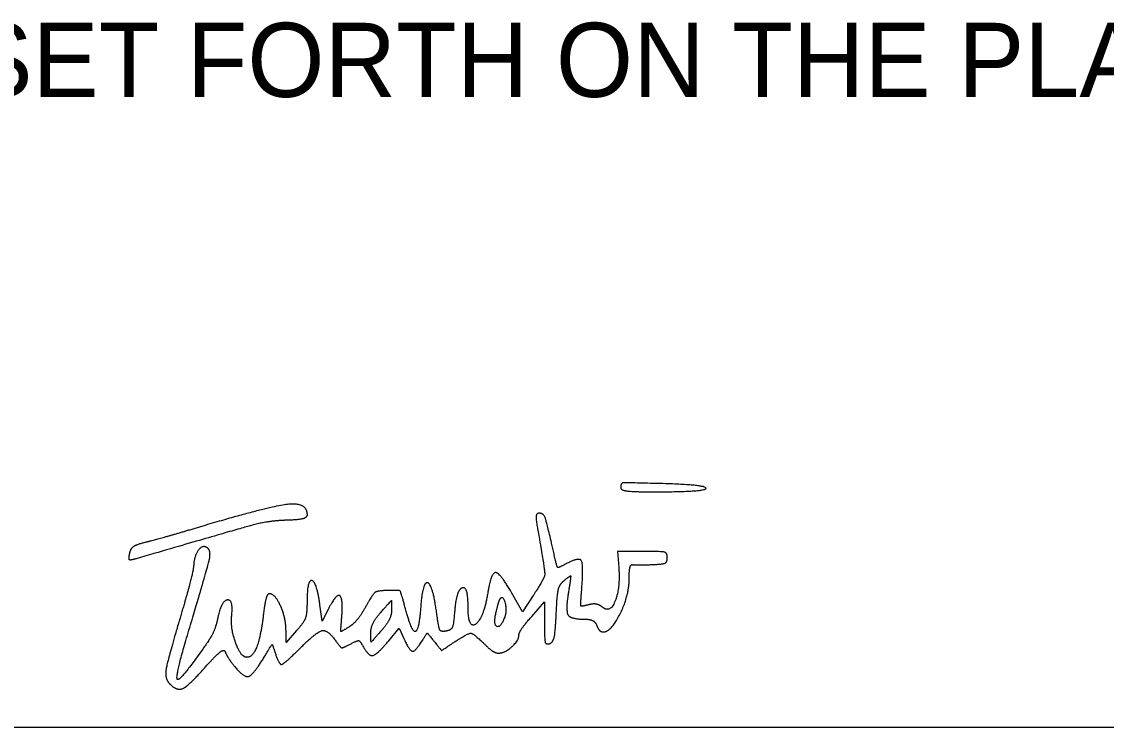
# Model space of a CAD drawing. Extents: x 0 to 34, y 0 to 22.
# Drawn here: x 25.697 to 27.744, y 8.816 to 10.148 of the extents above; entities that cross this region are included whole.
import ezdxf

# ---------------------------------------------------------------- set-up
doc = ezdxf.new("R2010")
doc.units = 0
doc.layers.add('SH_Data', color=7, linetype='Continuous')
doc.layers.add('SH_Text', color=7, linetype='Continuous')

msp = doc.modelspace()

# ---------------------------------------------------------------- linework, layer by layer
at = {"layer": 'SH_Data'}
msp.add_line((24.5, 8.816), (28, 8.816), dxfattribs=at)
at = {"layer": 'SH_Text'}
msp.add_line((25.9008, 9.1444), (25.9008, 9.1444), dxfattribs=at)
for points in [[(26.8687, 9.1481), (26.8218, 9.1481), (26.824, 9.118)], [(26.6626, 9.0651), (26.642, 9.0339), (26.6246, 9.0649)], [(26.6596, 9.0253), (26.6836, 9.0526), (26.6836, 9.0117)], [(26.2754, 9.0383), (26.2644, 9.0161), (26.26, 9.0474)], [(26.2159, 8.9985), (26.1961, 8.9761), (26.1959, 8.9985)], [(26.3899, 8.9795), (26.4096, 9.0029), (26.4184, 8.9835)]]:
    msp.add_lwpolyline(points, dxfattribs=at)
for points in [[(26.9025, 9.2761), (26.8357, 9.2779), (26.8276, 9.277), (26.8276, 9.2681)], [(26.9056, 9.2606), (26.99, 9.2611), (26.9875, 9.2738), (26.9025, 9.2761)], [(26.8276, 9.2681), (26.8276, 9.2633), (26.8586, 9.2603), (26.9056, 9.2606)], [(26.0398, 9.1966), (26.1652, 9.2339), (26.2356, 9.2413), (26.2356, 9.2171)], [(26.2356, 9.2171), (26.2356, 9.2118), (26.2198, 9.2076), (26.1974, 9.2069)], [(26.6743, 9.2201), (26.6684, 9.2201), (26.6675, 9.209), (26.6716, 9.1861)], [(26.703, 9.1379), (26.6886, 9.2017), (26.6822, 9.2201), (26.6743, 9.2201)], [(26.1974, 9.2069), (26.1654, 9.206), (26.1126, 9.1925), (25.9128, 9.1341)], [(25.9316, 9.1659), (25.947, 9.1696), (25.9957, 9.1834), (26.0398, 9.1966)], [(26.6716, 9.1861), (26.6849, 9.1112), (26.6839, 9.0973), (26.6626, 9.0651)], [(25.9008, 9.1444), (25.9026, 9.1535), (25.9143, 9.1617), (25.9316, 9.1659)], [(26.0111, 8.9943), (26.0457, 9.1098), (26.0549, 9.1475), (26.0494, 9.1529)], [(26.0494, 9.1529), (26.0407, 9.1617), (26.0233, 9.1427), (26.0216, 9.1224)], [(25.9128, 9.1341), (25.9017, 9.1309), (25.8987, 9.1334), (25.9008, 9.1444)], [(26.7247, 9.1246), (26.7099, 9.1168), (26.7074, 9.1183), (26.703, 9.1379)], [(26.7544, 9.0804), (26.7578, 9.124), (26.7488, 9.1375), (26.7247, 9.1246)], [(26.9156, 9.1361), (26.9156, 9.1454), (26.9051, 9.1481), (26.8687, 9.1481)], [(26.8856, 9.1231), (26.9065, 9.1238), (26.9156, 9.1277), (26.9156, 9.1361)], [(26.0216, 9.1224), (26.0208, 9.1122), (26.0092, 9.0671), (25.9958, 9.0222)], [(26.824, 9.118), (26.8268, 9.0779), (26.8075, 9.0308), (26.7932, 9.0428)], [(26.8436, 9.0948), (26.8436, 9.1109), (26.8463, 9.1236), (26.8496, 9.1231)], [(26.8496, 9.1231), (26.8529, 9.1226), (26.8691, 9.1226), (26.8856, 9.1231)], [(26.26, 9.0474), (26.2539, 9.0909), (26.2356, 9.0952), (26.2356, 9.0532)], [(26.6246, 9.0649), (26.6011, 9.1068), (26.5832, 9.1093), (26.5771, 9.0717)], [(26.706, 9.03), (26.7076, 9.0667), (26.7122, 9.0859), (26.7213, 9.0934)], [(26.7213, 9.0934), (26.733, 9.103), (26.7338, 9.101), (26.7292, 9.0726)], [(26.795, 8.9961), (26.8097, 8.9961), (26.8436, 9.0649), (26.8436, 9.0948)], [(26.3876, 9.0743), (26.3682, 9.0738), (26.3599, 9.0676), (26.3468, 9.0444)], [(26.4215, 9.0394), (26.4128, 9.0719), (26.4098, 9.075), (26.3876, 9.0743)], [(26.4797, 9.0356), (26.4726, 9.0866), (26.4536, 9.0912), (26.4501, 9.0427)], [(26.5396, 9.0441), (26.5396, 9.0835), (26.517, 9.0747), (26.5141, 9.0341)], [(26.5771, 9.0717), (26.569, 9.022), (26.5396, 9.0003), (26.5396, 9.0441)], [(26.7292, 9.0726), (26.7234, 9.0365), (26.7329, 9.0201), (26.7597, 9.0201)], [(26.7671, 9.0473), (26.7529, 9.0436), (26.7517, 9.0467), (26.7544, 9.0804)], [(26.0934, 9.0264), (26.0967, 9.0582), (26.0736, 9.0546), (26.067, 9.0223)], [(26.1645, 9.0681), (26.1608, 9.0681), (26.1558, 9.0508), (26.1533, 9.0297)], [(26.1959, 8.9985), (26.1956, 9.0229), (26.1752, 9.0681), (26.1645, 9.0681)], [(26.2356, 9.0532), (26.2356, 9.0303), (26.2299, 9.0144), (26.2159, 8.9985)], [(26.3012, 9.0249), (26.3041, 9.0611), (26.2902, 9.0683), (26.2754, 9.0383)], [(26.3753, 9.0336), (26.3942, 9.0551), (26.3951, 9.0553), (26.3953, 9.0385)], [(26.5926, 9.0341), (26.5955, 9.0462), (26.5991, 9.0575), (26.6005, 9.0592)], [(26.6005, 9.0592), (26.6061, 9.0657), (26.6131, 9.0356), (26.6087, 9.0241)], [(26.1533, 9.0297), (26.1483, 8.9877), (26.1331, 8.9481), (26.1219, 8.9481)], [(26.3468, 9.0444), (26.3378, 9.0283), (26.3233, 9.0107), (26.3146, 9.0053)], [(26.3559, 8.9936), (26.3557, 9.0033), (26.3645, 9.0213), (26.3753, 9.0336)], [(26.3953, 9.0385), (26.3955, 9.0289), (26.3867, 9.0109), (26.3759, 8.9985)], [(26.4501, 9.0427), (26.4467, 8.9976), (26.4331, 8.996), (26.4215, 9.0394)], [(26.4984, 8.9977), (26.4881, 8.9958), (26.484, 9.0041), (26.4797, 9.0356)], [(26.5141, 9.0341), (26.5123, 9.0103), (26.5077, 8.9995), (26.4984, 8.9977)], [(26.6087, 9.0241), (26.6004, 9.0025), (26.587, 9.0108), (26.5926, 9.0341)], [(26.6936, 8.974), (26.6999, 8.9761), (26.7045, 8.9968), (26.706, 9.03)], [(26.7932, 9.0428), (26.7874, 9.0475), (26.7757, 9.0496), (26.7671, 9.0473)], [(25.9958, 9.0222), (25.9718, 8.9412), (25.9667, 8.9076), (25.9769, 8.8974)], [(26.067, 9.0223), (26.0641, 9.0081), (26.056, 8.9883), (26.049, 8.9783)], [(26.1219, 8.9481), (26.1107, 8.9481), (26.0909, 9.0025), (26.0934, 9.0264)], [(26.3146, 9.0053), (26.2999, 8.9961), (26.299, 8.9974), (26.3012, 9.0249)], [(26.6356, 8.9903), (26.6356, 8.9945), (26.6464, 9.0103), (26.6596, 9.0253)], [(26.6836, 9.0117), (26.6836, 8.9825), (26.6865, 8.9717), (26.6936, 8.974)], [(26.7597, 9.0201), (26.7697, 9.0201), (26.78, 9.0147), (26.7825, 9.0081)], [(26.049, 8.9783), (25.997, 8.9036), (25.9853, 8.9085), (26.0111, 8.9943)], [(26.2239, 8.9667), (26.2539, 8.9967), (26.2746, 9.0005), (26.2901, 8.9788)], [(26.3759, 8.9985), (26.357, 8.977), (26.3561, 8.9768), (26.3559, 8.9936)], [(26.4529, 8.9792), (26.4621, 8.994), (26.4628, 8.9939), (26.476, 8.9776)], [(26.5126, 8.9762), (26.5392, 8.994), (26.5505, 8.9931), (26.5721, 8.9716)], [(26.597, 8.9561), (26.6087, 8.9561), (26.6356, 8.9799), (26.6356, 8.9903)], [(26.7825, 9.0081), (26.785, 9.0015), (26.7907, 8.9961), (26.795, 8.9961)], [(26.1548, 8.9486), (26.1691, 8.9722), (26.1703, 8.9727), (26.1753, 8.9569)], [(26.2901, 8.9788), (26.2986, 8.9667), (26.3036, 8.9657), (26.3172, 8.973)], [(26.3172, 8.973), (26.3306, 8.9801), (26.3354, 8.9793), (26.3412, 8.969)], [(26.3412, 8.969), (26.3519, 8.9498), (26.3678, 8.9532), (26.3899, 8.9795)], [(26.4184, 8.9835), (26.429, 8.9602), (26.4402, 8.9588), (26.4529, 8.9792)], [(26.476, 8.9776), (26.4894, 8.961), (26.4897, 8.961), (26.5126, 8.9762)], [(26.5721, 8.9716), (26.5806, 8.9631), (26.5918, 8.9561), (26.597, 8.9561)], [(26.044, 8.9301), (26.0639, 8.9524), (26.0793, 8.964), (26.0813, 8.9582)], [(26.0813, 8.9582), (26.0833, 8.9527), (26.0912, 8.9404), (26.099, 8.9308)], [(26.099, 8.9308), (26.1165, 8.9092), (26.1342, 8.9148), (26.1548, 8.9486)], [(26.1753, 8.9569), (26.1827, 8.9337), (26.1929, 8.9357), (26.2239, 8.9667)], [(25.9769, 8.8974), (25.9903, 8.884), (26.0129, 8.895), (26.044, 8.9301)]]:
    msp.add_open_spline(points, degree=2, dxfattribs=at)

# ---------------------------------------------------------------- texts
at = {"layer": 'SH_Data'}
msp.add_text('WILL BE AS SET FORTH ON THE PLANS AND ESTIMATES.', height=0.14, dxfattribs=at).set_placement((24.5, 10.006))

doc.saveas('drawing.dxf')
